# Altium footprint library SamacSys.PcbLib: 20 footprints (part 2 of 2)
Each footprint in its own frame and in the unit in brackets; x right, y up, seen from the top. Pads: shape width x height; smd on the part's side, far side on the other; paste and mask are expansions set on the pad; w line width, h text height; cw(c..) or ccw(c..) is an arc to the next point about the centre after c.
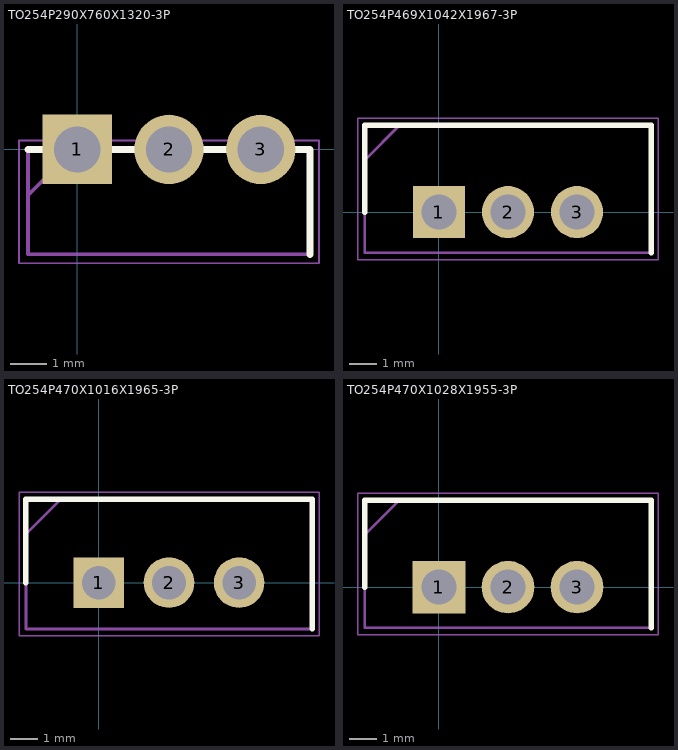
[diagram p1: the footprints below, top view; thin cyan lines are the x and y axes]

## TO254P290X760X1320-3P [mm]
pads (3):
  rect 1.92x1.92 hole 1.28: 1(0,0)
  round 1.92 hole 1.28: 2(2.54,0) 3(5.08,0)
Top Overlay:
  lines w0.2: -1.36,0 6.44,0 6.44,-2.9
Mechanical 13:
  lines w0.1: -1.36,-1.27 -0.09,0 ; -1.36,-2.9 -1.36,0 6.44,0 6.44,-2.9 -1.36,-2.9
Mechanical 15:
  lines w0.05: -1.61,-3.15 -1.61,0.25 6.69,0.25 6.69,-3.15 -1.61,-3.15
3D body "BD139.stp": height 12.93, standoff -21.55, extent -1.26,-2.9 6.34,0.255

## TO254P469X1042X1967-3P [mm]
pads (3):
  rect 1.92x1.92 hole 1.28: 1(0,0)
  round 1.92 hole 1.28: 2(2.54,0) 3(5.08,0)
Top Overlay:
  lines w0.2: -2.73,0 -2.73,3.195 7.81,3.195 7.81,-1.495
Mechanical 13:
  lines w0.1: -2.73,1.925 -1.46,3.195 ; -2.73,-1.495 -2.73,3.195 7.81,3.195 7.81,-1.495 -2.73,-1.495
Mechanical 15:
  lines w0.05: -2.98,-1.745 -2.98,3.445 8.06,3.445 8.06,-1.745 -2.98,-1.745
3D body "IRF540N.stp": height 18.84, standoff -17.51, extent -2.668,-1.495 7.748,3.195

## TO254P470X1016X1965-3P [mm]
pads (3):
  rect 1.83x1.83 hole 1.22: 1(0,0)
  round 1.83 hole 1.22: 2(2.54,0) 3(5.08,0)
Top Overlay:
  lines w0.2: -2.64,0 -2.64,3.025 7.72,3.025 7.72,-1.675
Mechanical 13:
  lines w0.1: -2.64,1.755 -1.37,3.025 ; -2.64,-1.675 -2.64,3.025 7.72,3.025 7.72,-1.675 -2.64,-1.675
Mechanical 15:
  lines w0.05: -2.89,-1.925 -2.89,3.275 7.97,3.275 7.97,-1.925 -2.89,-1.925
3D body "UA78M33CKCSE3.stp": height 21.39, standoff -6.97, extent -2.54,-1.61 7.62,2.96

## TO254P470X1028X1955-3P [mm]
pads (3):
  rect 1.935x1.935 hole 1.29: 1(0,0)
  round 1.935 hole 1.29: 2(2.54,0) 3(5.08,0)
Top Overlay:
  lines w0.2: -2.73,0 -2.73,3.2 7.81,3.2 7.81,-1.5
Mechanical 13:
  lines w0.1: -2.73,1.93 -1.46,3.2 ; -2.73,-1.5 -2.73,3.2 7.81,3.2 7.81,-1.5 -2.73,-1.5
Mechanical 15:
  lines w0.05: -2.98,-1.75 -2.98,3.45 8.06,3.45 8.06,-1.75 -2.98,-1.75
3D body "LM7805CT.stp": height 19.38, standoff -9.27, extent -2.54,-1.432 7.62,3.14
